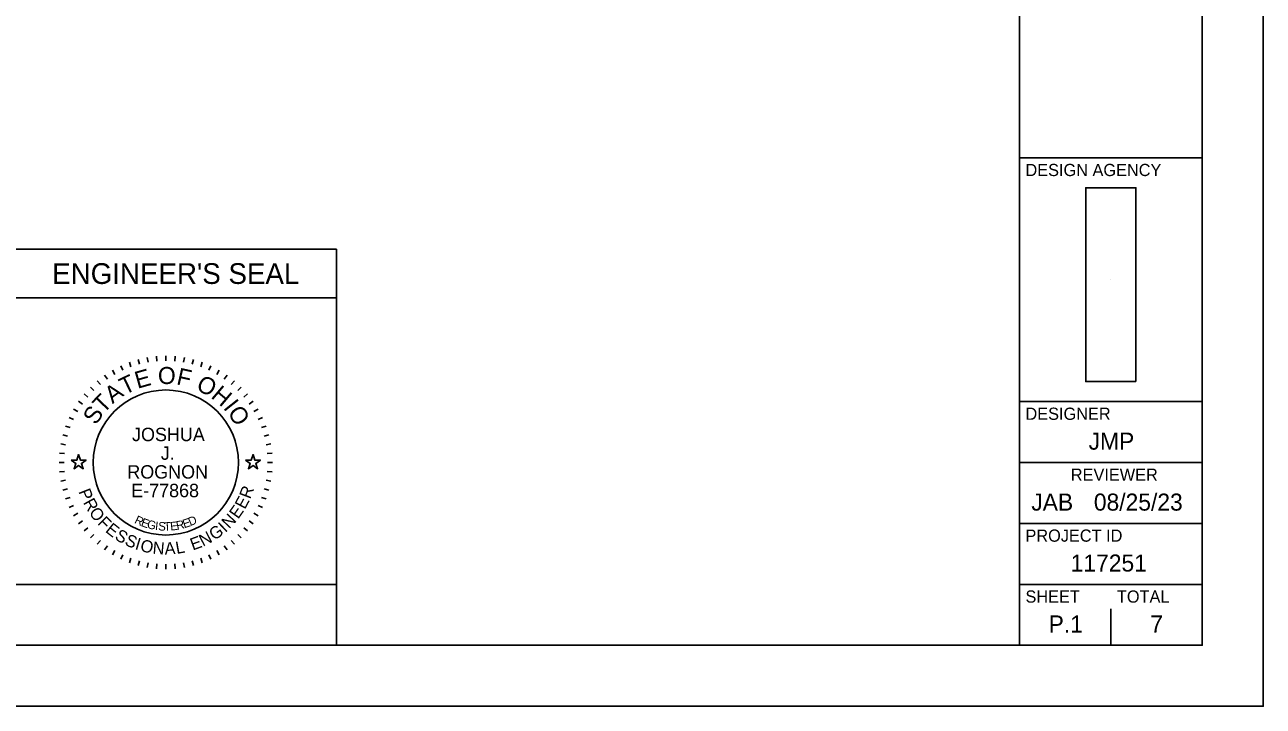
# Model space of a CAD drawing. Extents: x -8 to 42.1, y -22 to 0.
# Drawn here: x 23.84 to 34, y -22 to -16.41 of the extents above; entities that cross this region are included whole.
import ezdxf

# ---------------------------------------------------------------- set-up
doc = ezdxf.new("R2010")
doc.units = 0
for name, color, linetype in [('Default', 7, 'Continuous'), ('SH_Border', 7, 'Continuous'), ('SH_Cut_Line', 7, 'Continuous'), ('SH_Data', 7, 'Continuous'), ('SH_Text', 7, 'Continuous')]:
    doc.layers.add(name, color=color, linetype=linetype)

msp = doc.modelspace()

# ---------------------------------------------------------------- linework, layer by layer
at = {"layer": 'Default'}
for points in [[(24.224, -19.98), (24.271, -19.98), (24.285, -19.935), (24.299, -19.98), (24.346, -19.98), (24.308, -20.008), (24.323, -20.052), (24.285, -20.025), (24.247, -20.052), (24.262, -20.008)], [(25.654, -19.98), (25.701, -19.98), (25.715, -19.935), (25.729, -19.98), (25.776, -19.98), (25.738, -20.008), (25.753, -20.052), (25.715, -20.025), (25.677, -20.052), (25.692, -20.008)]]:
    msp.add_lwpolyline(points, close=True, dxfattribs=at)
at = {"layer": 'SH_Border'}
for p, q in [((32, -21.5), (32, -0.5)), ((32, -17.5), (33.5, -17.5)), ((32, -19.5), (33.5, -19.5)), ((32, -20), (33.5, -20)), ((32, -20.5), (33.5, -20.5)), ((32, -21), (33.5, -21))]:
    msp.add_line(p, q, dxfattribs=at)
msp.add_lwpolyline([(1.5, -0.5), (33.5, -0.5), (33.5, -21.5), (1.5, -21.5)], close=True, dxfattribs=at)
at = {"layer": 'SH_Cut_Line'}
msp.add_lwpolyline([(0, -22), (34, -22), (34, 0), (0, 0)], close=True, dxfattribs=at)
at = {"layer": 'SH_Data'}
for p, q in [((23.6, -18.25), (26.4, -18.25)), ((26.4, -18.25), (26.4, -21.5)), ((32.75, -18.5), (32.75, -18.5)), ((23.6, -18.65), (26.4, -18.65)), ((24.701, -19.178), (24.714, -19.215)), ((24.774, -19.155), (24.784, -19.193)), ((24.848, -19.138), (24.855, -19.178)), ((24.924, -19.128), (24.927, -19.168)), ((25, -19.125), (25, -19.165)), ((25.076, -19.128), (25.073, -19.168)), ((25.152, -19.138), (25.145, -19.178)), ((25.226, -19.155), (25.216, -19.193)), ((25.299, -19.178), (25.286, -19.215)), ((24.498, -19.283), (24.521, -19.316)), ((24.563, -19.242), (24.583, -19.277)), ((24.63, -19.207), (24.647, -19.243)), ((25.37, -19.207), (25.353, -19.243)), ((25.437, -19.242), (25.417, -19.277)), ((25.502, -19.283), (25.479, -19.316)), ((24.381, -19.381), (24.41, -19.41)), ((24.438, -19.33), (24.463, -19.36)), ((25.562, -19.33), (25.537, -19.36)), ((25.619, -19.381), (25.59, -19.41)), ((24.283, -19.498), (24.316, -19.521)), ((24.33, -19.438), (24.36, -19.463)), ((25.67, -19.438), (25.64, -19.463)), ((25.717, -19.498), (25.684, -19.521)), ((24.242, -19.562), (24.277, -19.582)), ((25.758, -19.562), (25.723, -19.582)), ((24.178, -19.701), (24.215, -19.714)), ((24.207, -19.63), (24.243, -19.647)), ((25.793, -19.63), (25.757, -19.647)), ((25.822, -19.701), (25.785, -19.714)), ((24.155, -19.774), (24.193, -19.784)), ((25.845, -19.774), (25.807, -19.784)), ((24.138, -19.848), (24.178, -19.855)), ((25.862, -19.848), (25.822, -19.855)), ((24.125, -20), (24.165, -20)), ((24.128, -19.924), (24.168, -19.927)), ((25.872, -19.924), (25.832, -19.927)), ((25.875, -20), (25.835, -20)), ((24.128, -20.076), (24.168, -20.073)), ((25.872, -20.076), (25.832, -20.073)), ((24.138, -20.152), (24.178, -20.145)), ((25.862, -20.152), (25.822, -20.145)), ((24.155, -20.226), (24.193, -20.216)), ((24.178, -20.299), (24.215, -20.286)), ((25.822, -20.299), (25.785, -20.286)), ((25.845, -20.226), (25.807, -20.216)), ((24.207, -20.37), (24.243, -20.353)), ((25.793, -20.37), (25.757, -20.353)), ((24.242, -20.437), (24.277, -20.417)), ((24.283, -20.502), (24.316, -20.479)), ((25.717, -20.502), (25.684, -20.479)), ((25.758, -20.437), (25.723, -20.417)), ((24.33, -20.562), (24.36, -20.537)), ((24.381, -20.619), (24.41, -20.59)), ((25.619, -20.619), (25.59, -20.59)), ((25.67, -20.562), (25.64, -20.537)), ((24.438, -20.67), (24.463, -20.64)), ((24.498, -20.717), (24.521, -20.684)), ((25.502, -20.717), (25.479, -20.684)), ((25.562, -20.67), (25.537, -20.64)), ((24.563, -20.758), (24.583, -20.723)), ((24.63, -20.793), (24.647, -20.757)), ((24.701, -20.822), (24.714, -20.785)), ((24.774, -20.845), (24.784, -20.807)), ((25.226, -20.845), (25.216, -20.807)), ((25.299, -20.822), (25.286, -20.785)), ((25.37, -20.793), (25.353, -20.757)), ((25.437, -20.758), (25.417, -20.723)), ((24.848, -20.862), (24.855, -20.822)), ((24.924, -20.872), (24.927, -20.832)), ((25, -20.875), (25, -20.835)), ((25.076, -20.872), (25.073, -20.832)), ((25.152, -20.862), (25.145, -20.822)), ((32.75, -21.5), (32.75, -21.2)), ((32.375, -21.325), (32.375, -21.325)), ((23.6, -21.5), (26.4, -21.5)), ((23.6, -21.5), (26.4, -21.5))]:
    msp.add_line(p, q, dxfattribs=at)
msp.add_lwpolyline([(23.6, -21.5), (23.6, -21), (26.4, -21), (26.4, -21.5)], close=True, dxfattribs=at)
msp.add_circle((25, -20), 0.595, dxfattribs=at)
at = {"layer": 'SH_Text'}
msp.add_lwpolyline([(32.956, -19.336), (32.956, -17.746), (32.544, -17.746), (32.544, -19.336)], close=True, dxfattribs=at)

# ---------------------------------------------------------------- texts
at = {"layer": 'SH_Data'}
for s, height, p in [('DESIGN AGENCY', 0.1, (32.05, -17.65)), ("ENGINEER'S SEAL", 0.17, (24.068, -18.535)), ('DESIGNER', 0.1, (32.05, -19.65)), ('JOSHUA', 0.11, (24.723, -19.825)), ('JMP', 0.14, (32.568, -19.895)), ('J.', 0.11, (24.959, -19.978)), ('ROGNON', 0.11, (24.684, -20.132)), ('REVIEWER', 0.1, (32.422, -20.15)), ('E-77868', 0.11, (24.716, -20.285)), ('JAB', 0.14, (32.098, -20.395)), ('08/25/23', 0.14, (32.611, -20.395)), ('PROJECT ID', 0.1, (32.05, -20.65)), ('117251', 0.14, (32.421, -20.895)), ('SHEET', 0.1, (32.05, -21.15)), ('TOTAL', 0.1, (32.8, -21.15)), ('P.1', 0.14, (32.24, -21.395)), ('7', 0.14, (33.074, -21.395))]:
    msp.add_text(s, height=height, dxfattribs=at).set_placement(p)
for s, height, rotation, p in [('T', 0.14, 25.7167, (24.662, -19.448)), ('E', 0.14, 15.7571, (24.768, -19.396)), ('O', 0.14, 359.7812, (24.935, -19.356)), ('F', 0.14, 347.4362, (25.081, -19.358)), ('O', 0.14, 332.2586, (25.24, -19.398)), ('A', 0.14, 36.4747, (24.563, -19.522)), ('H', 0.14, 319.9136, (25.363, -19.464)), ('T', 0.14, 46.4344, (24.488, -19.604)), ('I', 0.14, 308.367, (25.466, -19.552)), ('S', 0.14, 57.1924, (24.428, -19.699)), ('O', 0.14, 303.1491, (25.502, -19.591)), ('P', 0.1, 291.494, (24.282, -20.238)), ('R', 0.1, 69.2322, (25.692, -20.305)), ('R', 0.1, 298.7311, (24.319, -20.328)), ('E', 0.1, 61.9951, (25.648, -20.39)), ('O', 0.1, 306.4666, (24.365, -20.412)), ('E', 0.1, 54.758, (25.593, -20.469)), ('F', 0.1, 314.7068, (24.434, -20.502)), ('E', 0.1, 321.4393, (24.498, -20.565)), ('R', 0.07, 334.487, (24.737, -20.495)), ('E', 0.07, 341.04, (24.791, -20.52)), ('G', 0.07, 347.4752, (24.841, -20.538)), ('I', 0.07, 353.7858, (24.909, -20.553)), ('S', 0.07, 356.8926, (24.936, -20.557)), ('T', 0.07, 3.0061, (24.986, -20.561)), ('E', 0.07, 6.0117, (25.039, -20.559)), ('R', 0.07, 11.9184, (25.092, -20.553)), ('E', 0.07, 17.6836, (25.15, -20.54)), ('D', 0.07, 23.3052, (25.201, -20.523)), ('I', 0.1, 43.287, (25.487, -20.579)), ('N', 0.1, 47.0224, (25.52, -20.549)), ('S', 0.1, 328.6764, (24.574, -20.625)), ('S', 0.1, 335.9134, (24.656, -20.673)), ('I', 0.1, 343.1505, (24.741, -20.71)), ('E', 0.1, 20.0742, (25.221, -20.723)), ('N', 0.1, 27.3113, (25.304, -20.692)), ('G', 0.1, 35.0469, (25.398, -20.643)), ('O', 0.1, 346.8859, (24.784, -20.725)), ('N', 0.1, 355.1261, (24.889, -20.748)), ('A', 0.1, 2.8617, (24.992, -20.756)), ('L', 0.1, 10.0987, (25.089, -20.751))]:
    msp.add_text(s, height=height, rotation=rotation, dxfattribs=at).set_placement(p)

doc.saveas('drawing.dxf')
